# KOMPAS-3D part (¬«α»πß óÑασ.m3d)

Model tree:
1. Эскиз:1
2. Операция выдавливания:1
     Расстояние 1 = 2; Расстояние 2 = 1
3. Эскиз:2
4. Вырезать элемент выдавливания:1
     Расстояние 1 = 2
5. Эскиз:3
6. Вырезать элемент выдавливания:2
     Расстояние 1 = 2
7. Эскиз:4
8. Вырезать элемент выдавливания:3
     Расстояние 1 = 2
9. Скругление:1
     Радиус = 0.5
10. Скругление:2
     Радиус = 0.5
11. Эскиз:5
12. Операция выдавливания:2
     Расстояние 1 = 1.5
13. Эскиз:6
14. Операция выдавливания:3
     Расстояние 1 = 2
15. Скругление:3
     Радиус = 1
16. Эскиз:7
17. Операция выдавливания:4
     Расстояние 1 = 2
18. Эскиз:8
19. Операция выдавливания:5
     Расстояние 1 = 1
20. Эскиз:9
21. Вырезать элемент выдавливания:4
     Расстояние 1 = 0.3
22. Эскиз:10
23. Операция выдавливания:6
     Расстояние 1 = 0.2
24. Эскиз:11
25. Вырезать элемент выдавливания:5
     Расстояние 1 = 0.1
26. Эскиз:12
27. Операция выдавливания:7
     Расстояние 1 = 0.5
28. Эскиз:13
29. Операция выдавливания:8
     Расстояние 1 = 0.3
30. Эскиз:14
31. Операция выдавливания:9
     Расстояние 1 = 0.3
32. Эскиз:15
33. Операция выдавливания:10
     Расстояние 1 = 0.3
34. Эскиз:16
35. Операция выдавливания:11
     Расстояние 1 = 1
36. Эскиз:17
37. Вырезать элемент выдавливания:6
     Расстояние 1 = 0.3
38. Эскиз:18
39. Операция выдавливания:12
     Расстояние 1 = 1
40. Скругление:4
     Радиус = 0.5
41. Фаска:1
     Угол = 45; Длина 1 = 1; Длина 2 = 1
42. Эскиз:19
43. Операция выдавливания:13
     Расстояние 1 = 0.5
44. Эскиз:20
45. Вырезать элемент выдавливания:7
     Расстояние 1 = 0.2
46. Эскиз:21
47. Вырезать элемент выдавливания:8
     Расстояние 1 = 0.4
48. Эскиз:22
49. Операция выдавливания:14
     Расстояние 1 = 0.5
50. Эскиз:23
51. Операция выдавливания:15
     Расстояние 1 = 2
52. Эскиз:24
53. Операция выдавливания:16
     Расстояние 1 = 2.2
54. Эскиз:25
55. Операция выдавливания:17
     Расстояние 1 = 2
56. Эскиз:26
57. Вырезать элемент выдавливания:9
     Расстояние 1 = 0.3
58. Эскиз:27
59. Операция выдавливания:18
     Расстояние 1 = 0.3
60. Эскиз:28
61. Операция выдавливания:19
     Расстояние 1 = 1.4

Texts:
  Сплав АЛ8  ГОСТ 1583-93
